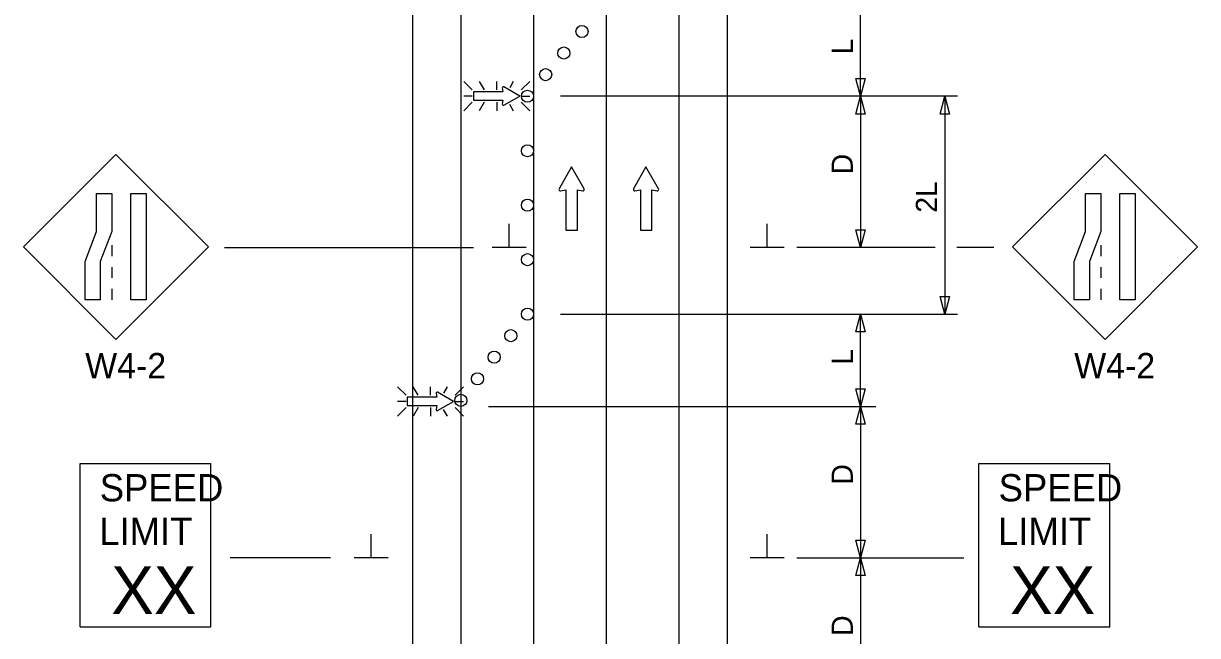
# Model space of a CAD drawing. Extents: x 16576 to 19508, y 5728 to 6974.
# Drawn here: x 17817.2 to 18204.9, y 6468 to 6670.3 of the extents above; entities that cross this region are included whole.
import ezdxf

# ---------------------------------------------------------------- set-up
doc = ezdxf.new("R2010")
doc.units = 0
for name, color, linetype in [('ALI_LEGAL_EX', 7, 'Continuous'), ('MT_SCRATCH_LEVEL_E', 7, 'Continuous'), ('PAVT_EDGE_EX', 7, 'Continuous'), ('TRAFFIC_SIGNS_PR', 7, 'Continuous'), ('TYPICAL_TEXT_DIMEN_PR', 7, 'Continuous')]:
    doc.layers.add(name, color=color, linetype=linetype)

msp = doc.modelspace()

# ---------------------------------------------------------------- linework, layer by layer
at = {"layer": 'ALI_LEGAL_EX'}
for p, q in [((17985.63, 6921.33), (17985.63, 6077.19)), ((18009.63, 6921.33), (18009.63, 6077.19))]:
    msp.add_line(p, q, dxfattribs=at)
for points in [[(17985.63, 6621.33), (17985.63, 6596.33)], [(18009.63, 6621.33), (18009.63, 6596.33)], [(17985.63, 6521.33), (17985.63, 6496.33)], [(18009.63, 6521.33), (18009.63, 6496.33)]]:
    msp.add_lwpolyline(points, dxfattribs=at)
at = {"layer": 'MT_SCRATCH_LEVEL_E'}
for p, q in [((17998.21, 6622.84), (17994.1, 6615.6)), ((18002.35, 6615.6), (17998.21, 6622.84)), ((18022.77, 6622.84), (18018.65, 6615.6)), ((18026.91, 6615.6), (18022.77, 6622.84)), ((17994.58, 6614.92), (17996.35, 6615.24)), ((17996.35, 6615.24), (17996.35, 6601.98)), ((18000.1, 6601.98), (18000.1, 6615.24)), ((18000.1, 6615.24), (18001.87, 6614.92)), ((18019.14, 6614.92), (18020.91, 6615.24)), ((18020.91, 6615.24), (18020.91, 6601.98)), ((18024.66, 6601.98), (18024.66, 6615.24)), ((18024.66, 6615.24), (18026.43, 6614.92)), ((17996.35, 6601.98), (18000.1, 6601.98)), ((18020.91, 6601.98), (18024.66, 6601.98))]:
    msp.add_line(p, q, dxfattribs=at)
for centre, start, end in [((17994.5, 6615.38), 150.4248, 279.9638), ((18001.94, 6615.38), 260.0362, 29.7731), ((18019.06, 6615.38), 150.4248, 279.9638), ((18026.5, 6615.38), 260.0362, 29.7731)]:
    msp.add_arc(centre, 0.463, start, end, dxfattribs=at)
at = {"layer": 'PAVT_EDGE_EX'}
for p, q in [((17945.63, 6921.33), (17945.63, 5988.51)), ((17961.63, 6921.33), (17961.63, 5988.51)), ((18033.63, 6921.33), (18033.63, 5988.51)), ((18049.63, 6921.33), (18049.63, 5988.51))]:
    msp.add_line(p, q, dxfattribs=at)
at = {"layer": 'TRAFFIC_SIGNS_PR'}
for p, q in [((17965.41, 6648.3), (17962.59, 6651.12)), ((17967.71, 6651.12), (17969.33, 6648.3)), ((17973.49, 6648.3), (17973.49, 6651.12)), ((17978.96, 6651.12), (17977.76, 6649.02)), ((17984.4, 6651.11), (17981.58, 6648.3)), ((17965.41, 6646.27), (17962.59, 6646.27)), ((17981.58, 6646.27), (17984.4, 6646.27)), ((17965.41, 6644.23), (17962.59, 6641.41)), ((17969.36, 6644.23), (17967.73, 6641.41)), ((17973.49, 6644.23), (17973.49, 6641.41)), ((17977.68, 6643.6), (17978.94, 6641.41)), ((17984.4, 6641.41), (17981.58, 6644.23)), ((17847.75, 6626.95), (17817.2, 6596.4)), ((17878.3, 6596.4), (17847.75, 6626.95)), ((18174.35, 6626.95), (18143.81, 6596.4)), ((18204.9, 6596.4), (18174.35, 6626.95)), ((17817.2, 6596.4), (17847.75, 6565.85)), ((17846.35, 6596.95), (17846.35, 6593.35)), ((17847.75, 6565.85), (17878.3, 6596.4)), ((18143.81, 6596.4), (18174.35, 6565.85)), ((18172.95, 6596.95), (18172.95, 6593.35)), ((18174.35, 6565.85), (18204.9, 6596.4)), ((17846.35, 6589.75), (17846.35, 6586.15)), ((18172.95, 6589.75), (18172.95, 6586.15)), ((17846.35, 6582.55), (17846.35, 6578.95)), ((18172.95, 6582.55), (18172.95, 6578.95)), ((17943.54, 6547.35), (17940.72, 6550.17)), ((17945.83, 6550.16), (17947.46, 6547.35)), ((17951.62, 6547.35), (17951.62, 6550.16)), ((17957.09, 6550.16), (17955.88, 6548.07)), ((17962.53, 6550.16), (17959.71, 6547.35)), ((17943.54, 6545.31), (17940.72, 6545.31)), ((17959.71, 6545.31), (17962.53, 6545.31)), ((17943.54, 6543.28), (17940.72, 6540.46)), ((17947.49, 6543.28), (17945.86, 6540.46)), ((17951.62, 6543.28), (17951.62, 6540.46)), ((17955.8, 6542.65), (17957.06, 6540.46)), ((17962.53, 6540.46), (17959.71, 6543.28)), ((17835.91, 6524.84), (17879.11, 6524.84)), ((17835.91, 6470.84), (17835.91, 6524.84)), ((17879.11, 6470.84), (17879.11, 6524.84)), ((18132.73, 6524.84), (18175.93, 6524.84)), ((18132.73, 6470.84), (18132.73, 6524.84)), ((18175.93, 6470.84), (18175.93, 6524.84)), ((17835.91, 6470.84), (17879.11, 6470.84)), ((18132.73, 6470.84), (18175.93, 6470.84))]:
    msp.add_line(p, q, dxfattribs=at)
for points in [[(17975.82, 6643.25), (17981.13, 6646.27), (17975.82, 6649.31)], [(17975.32, 6648.95), (17975.55, 6647.65), (17965.83, 6647.65), (17965.83, 6644.91), (17975.55, 6644.91), (17975.32, 6643.6)], [(17953.95, 6542.3), (17959.26, 6545.31), (17953.95, 6548.35)], [(17953.45, 6547.99), (17953.68, 6546.7), (17943.96, 6546.7), (17943.96, 6543.95), (17953.68, 6543.95), (17953.45, 6542.65)]]:
    msp.add_lwpolyline(points, dxfattribs=at)
for points in [[(17846.35, 6614.1), (17846.35, 6601.52), (17842.58, 6591.53), (17842.58, 6578.95), (17837.53, 6578.95), (17837.53, 6591.53), (17841.29, 6601.52), (17841.29, 6614.1)], [(17857.75, 6614.1), (17857.75, 6578.95), (17852.7, 6578.95), (17852.7, 6614.1)], [(18172.95, 6614.1), (18172.95, 6601.52), (18169.19, 6591.53), (18169.19, 6578.95), (18164.13, 6578.95), (18164.13, 6591.53), (18167.89, 6601.52), (18167.89, 6614.1)], [(18184.35, 6614.1), (18184.35, 6578.95), (18179.3, 6578.95), (18179.3, 6614.1)]]:
    msp.add_lwpolyline(points, close=True, dxfattribs=at)
for centre in [(18001.63, 6667.62), (17995.63, 6660.48), (17989.63, 6653.34), (17983.63, 6646.2), (17983.63, 6628.19), (17983.63, 6610.19), (17983.63, 6592.19), (17983.63, 6574.19), (17978.14, 6567.06), (17972.64, 6559.94), (17967.14, 6552.81), (17961.64, 6545.68)]:
    msp.add_circle(centre, 2, dxfattribs=at)
for centre, start, end in [((17975.66, 6649.01), 61.4833, 189.9593), ((17975.66, 6643.55), 170.7308, 298.8916), ((17953.78, 6548.05), 61.4833, 189.9593), ((17953.78, 6542.6), 170.7308, 298.8916)]:
    msp.add_arc(centre, 0.341, start, end, dxfattribs=at)
at = {"layer": 'TYPICAL_TEXT_DIMEN_PR'}
for p, q in [((18093.63, 6646.19), (18093.63, 6676.76)), ((18093.63, 6646.19), (18092.06, 6652.06)), ((18092.06, 6652.06), (18093.63, 6652.06)), ((18093.63, 6652.06), (18095.2, 6652.06)), ((18095.2, 6652.06), (18093.63, 6646.19)), ((18125.68, 6646.19), (17994.53, 6646.19)), ((18092.06, 6640.33), (18093.63, 6646.19)), ((18093.63, 6646.19), (18093.63, 6596.19)), ((18093.63, 6646.19), (18095.2, 6640.33)), ((18119.87, 6640.33), (18121.44, 6646.19)), ((18121.44, 6646.19), (18123.01, 6640.33)), ((18121.44, 6646.19), (18121.44, 6595.96)), ((18093.63, 6640.33), (18092.06, 6640.33)), ((18095.2, 6640.33), (18093.63, 6640.33)), ((18121.44, 6640.33), (18119.87, 6640.33)), ((18123.01, 6640.33), (18121.44, 6640.33)), ((17977.56, 6596.19), (17977.56, 6603.98)), ((18062.76, 6596.19), (18062.76, 6603.98)), ((18093.63, 6596.19), (18092.06, 6602.06)), ((18092.06, 6602.06), (18093.63, 6602.06)), ((18093.63, 6602.06), (18095.2, 6602.06)), ((18095.2, 6602.06), (18093.63, 6596.19)), ((18121.44, 6601.06), (18121.44, 6597.3)), ((17883.63, 6596.19), (17965.83, 6596.19)), ((17983.19, 6596.19), (17971.94, 6596.19)), ((18068.38, 6596.19), (18057.13, 6596.19)), ((18118.25, 6596.19), (18072.63, 6596.19)), ((18121.44, 6595.96), (18121.44, 6574.19)), ((18137.63, 6596.19), (18125.38, 6596.19)), ((18121.44, 6574.19), (18119.87, 6580.06)), ((18119.87, 6580.06), (18121.44, 6580.06)), ((18121.44, 6580.06), (18123.01, 6580.06)), ((18123.01, 6580.06), (18121.44, 6574.19)), ((17994.53, 6574.19), (18125.68, 6574.19)), ((18092.06, 6568.33), (18093.63, 6574.19)), ((18093.63, 6543.63), (18093.63, 6574.19)), ((18093.63, 6574.19), (18095.2, 6568.33)), ((18093.63, 6568.33), (18092.06, 6568.33)), ((18095.2, 6568.33), (18093.63, 6568.33)), ((18093.63, 6543.63), (18092.06, 6549.49)), ((18092.06, 6549.49), (18093.63, 6549.49)), ((18093.63, 6549.49), (18095.2, 6549.49)), ((18095.2, 6549.49), (18093.63, 6543.63)), ((17970.8, 6543.63), (18098.63, 6543.63)), ((18092.06, 6537.77), (18093.63, 6543.63)), ((18093.63, 6543.63), (18093.63, 6493.63)), ((18093.63, 6543.63), (18095.2, 6537.77)), ((18093.63, 6537.77), (18092.06, 6537.77)), ((18095.2, 6537.77), (18093.63, 6537.77)), ((17932.02, 6493.63), (17932.02, 6501.41)), ((18062.76, 6493.63), (18062.76, 6501.41)), ((18093.63, 6493.63), (18092.06, 6499.49)), ((18092.06, 6499.49), (18093.63, 6499.49)), ((18093.63, 6499.49), (18095.2, 6499.49)), ((18095.2, 6499.49), (18093.63, 6493.63)), ((17918.58, 6493.63), (17885.49, 6493.63)), ((17937.64, 6493.63), (17926.39, 6493.63)), ((18068.38, 6493.63), (18057.13, 6493.63)), ((18072.63, 6493.63), (18127.76, 6493.63)), ((18092.06, 6487.77), (18093.63, 6493.63)), ((18093.63, 6493.63), (18093.63, 6443.63)), ((18093.63, 6493.63), (18095.2, 6487.77)), ((18093.63, 6487.77), (18092.06, 6487.77)), ((18095.2, 6487.77), (18093.63, 6487.77))]:
    msp.add_line(p, q, dxfattribs=at)

# ---------------------------------------------------------------- texts
at = {"layer": 'TRAFFIC_SIGNS_PR'}
for s, height, p in [('W4-2', 8.37, (17837.58, 6552.98)), ('W4-2', 8.37, (18164.18, 6552.98)), ('SPEED', 9, (17842.4, 6512.31)), ('SPEED', 9, (18139.22, 6512.31)), ('LIMIT', 9, (17842.22, 6497.91)), ('LIMIT', 9, (18139.04, 6497.91)), ('XX', 15.785, (17846.17, 6475.06)), ('XX', 15.785, (18142.98, 6475.06))]:
    msp.add_text(s, height=height, dxfattribs=at).set_placement(p)
at = {"layer": 'TYPICAL_TEXT_DIMEN_PR'}
for s, p in [('L', (18091.08, 6660.05)), ('D', (18091.08, 6620.41)), ('2L', (18118.88, 6607.7)), ('L', (18091.08, 6557.49)), ('D', (18091.08, 6517.85)), ('D', (18091.08, 6467.85))]:
    msp.add_text(s, height=7, rotation=90, dxfattribs=at).set_placement(p)

doc.saveas('drawing.dxf')
